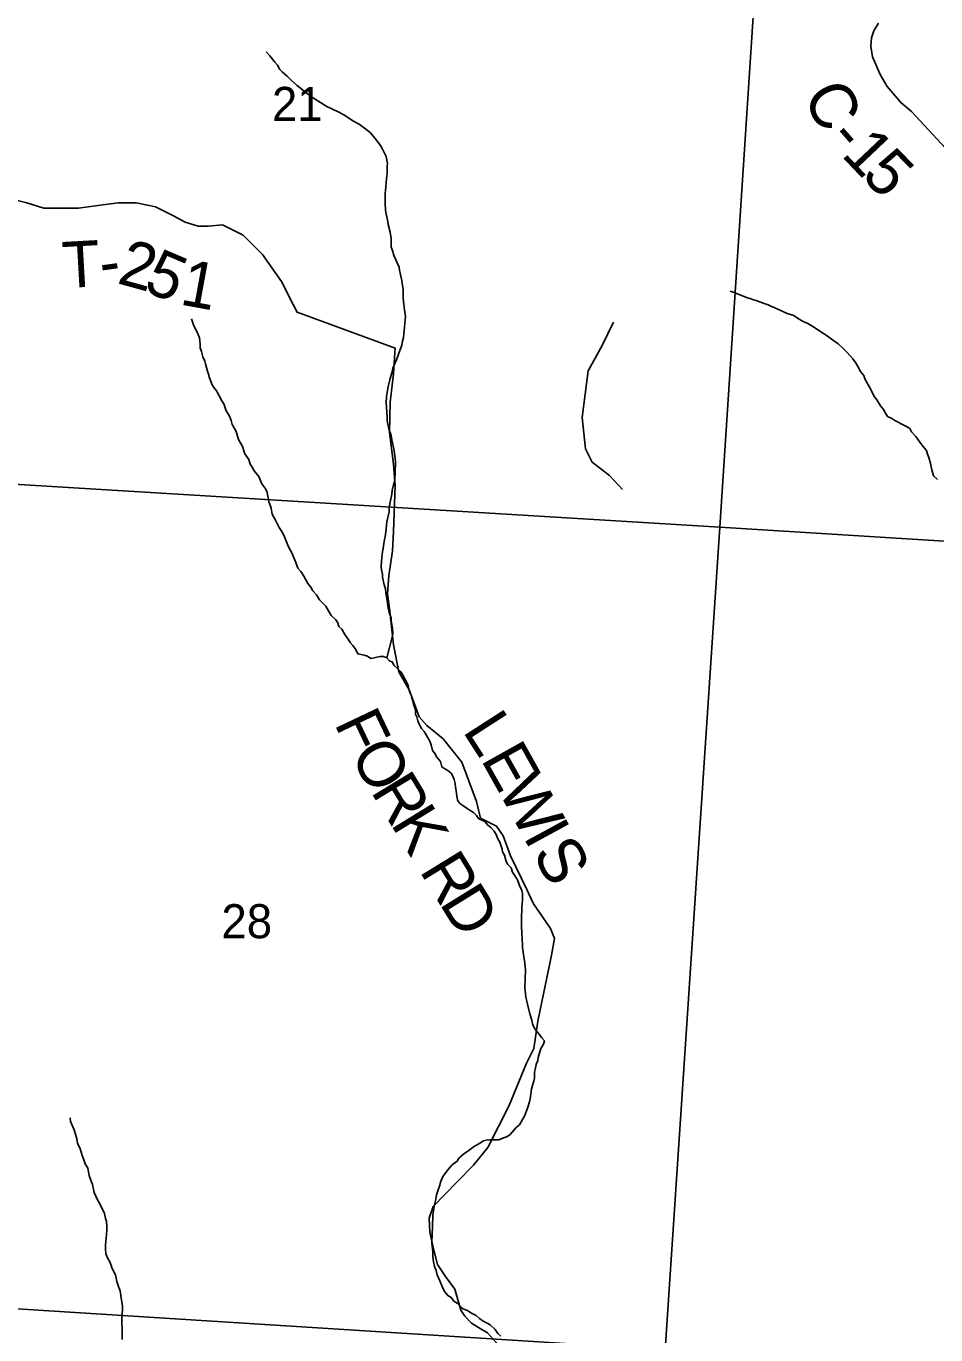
# Model space of a CAD drawing. Extents: x 0 to 34, y 0 to 22.
# Drawn here: x 4.939 to 6.056, y 16.966 to 18.575 of the extents above; entities that cross this region are included whole.
import ezdxf

# ---------------------------------------------------------------- set-up
doc = ezdxf.new("R2010")
doc.units = 0
for name, color, linetype in [('GM_X_County_Road', 7, 'Continuous'), ('GM_X_County_Road_Text', 7, 'Continuous'), ('GM_X_Minor_River', 7, 'Continuous'), ('GM_X_Section', 7, 'Continuous'), ('GM_X_Section_Text', 7, 'Continuous'), ('GM_X_Township_Road', 7, 'Continuous'), ('GM_X_Township_Road_Text', 7, 'Continuous'), ('GM_X_Township_ROW', 7, 'Continuous')]:
    doc.layers.add(name, color=color, linetype=linetype)

msp = doc.modelspace()

# ---------------------------------------------------------------- linework, layer by layer
at = {"layer": 'GM_X_County_Road'}
msp.add_lwpolyline([(5.9857, 18.5785), (5.9803, 18.569), (5.9774, 18.5607), (5.9765, 18.5503), (5.9786, 18.5374), (5.9877, 18.5154), (5.9965, 18.5009), (6.0135, 18.4806), (6.0263, 18.4702), (6.0945, 18.3967)], dxfattribs=at)
at = {"layer": 'GM_X_Minor_River'}
for points in [[(5.2805, 18.4945), (5.2716, 18.5018), (5.2645, 18.508), (5.2593, 18.5134), (5.2537, 18.5185), (5.2503, 18.5216), (5.2474, 18.5269), (5.2441, 18.5308), (5.2378, 18.5385), (5.2333, 18.5435)], [(5.3816, 17.7984), (5.3889, 17.8256), (5.389, 17.829), (5.3887, 17.8347), (5.3869, 17.8439), (5.387, 17.8477), (5.3848, 17.8542), (5.3831, 17.8622), (5.3821, 17.8687), (5.3804, 17.879), (5.38, 17.8832), (5.3786, 17.8881), (5.3765, 17.8977), (5.3766, 17.9015), (5.3752, 17.9068), (5.3748, 17.9102), (5.3753, 17.9175), (5.3754, 17.922), (5.3759, 17.9258), (5.3767, 17.9307), (5.3788, 17.944), (5.3797, 17.9474), (5.381, 17.9565), (5.3814, 17.9615), (5.3819, 17.9656), (5.3844, 17.9778), (5.3845, 17.9838), (5.3853, 17.988), (5.3878, 17.9997), (5.3882, 18.0043), (5.3915, 18.0179), (5.392, 18.0259), (5.3922, 18.0392), (5.3919, 18.0434), (5.3913, 18.0495), (5.3903, 18.0556), (5.3878, 18.0663), (5.3871, 18.0716), (5.3843, 18.08), (5.3822, 18.0899), (5.3822, 18.0937), (5.3816, 18.101), (5.381, 18.112), (5.3812, 18.1196), (5.3828, 18.1294), (5.3837, 18.1336), (5.3853, 18.1404), (5.3881, 18.1499), (5.389, 18.1544), (5.3937, 18.165), (5.3961, 18.1718), (5.4001, 18.1827), (5.4005, 18.1862), (5.4021, 18.1922), (5.4035, 18.2051), (5.404, 18.21), (5.4045, 18.218), (5.4035, 18.2264), (5.4025, 18.2329), (5.4018, 18.2405), (5.4019, 18.2447), (5.4016, 18.2507), (5.4006, 18.2591), (5.4003, 18.2625), (5.3989, 18.2675), (5.3971, 18.2748), (5.3968, 18.2786), (5.3939, 18.2847), (5.3899, 18.2943), (5.3892, 18.2981), (5.387, 18.3031), (5.3871, 18.3099), (5.3872, 18.3141), (5.3858, 18.3217), (5.3834, 18.3312), (5.383, 18.335), (5.3806, 18.3457), (5.3803, 18.3495), (5.3796, 18.356), (5.3797, 18.3602), (5.3795, 18.3697), (5.3799, 18.3731), (5.3804, 18.3773), (5.3813, 18.3871), (5.3822, 18.394), (5.3823, 18.4027), (5.3824, 18.4061), (5.381, 18.4149), (5.3748, 18.4268), (5.3689, 18.4348), (5.3615, 18.4437), (5.3544, 18.4495), (5.3476, 18.4546), (5.3398, 18.4585), (5.3296, 18.4655), (5.3221, 18.4694), (5.3082, 18.4761), (5.297, 18.4832), (5.2891, 18.4882), (5.2805, 18.4945)], [(6.0585, 18.0178), (6.0533, 18.0224), (6.0515, 18.0297), (6.0498, 18.0373), (6.0476, 18.0446), (6.0462, 18.0488), (6.0447, 18.0534), (6.0403, 18.0588), (6.0366, 18.0638), (6.0318, 18.0707), (6.0262, 18.0761), (6.0244, 18.0803), (6.0203, 18.083), (6.0161, 18.085), (6.0067, 18.0897), (6.0015, 18.0932), (5.997, 18.0952), (5.9944, 18.0991), (5.9918, 18.1037), (5.9881, 18.1083), (5.9837, 18.1156), (5.9811, 18.1194), (5.9786, 18.124), (5.976, 18.129), (5.969, 18.1413), (5.9679, 18.1455), (5.9639, 18.1505), (5.9606, 18.1566), (5.9576, 18.1616), (5.9543, 18.1659), (5.9476, 18.1736), (5.9416, 18.1794), (5.9361, 18.1844), (5.9293, 18.1895), (5.9226, 18.1941), (5.9162, 18.1984), (5.9072, 18.2047), (5.899, 18.2094), (5.8934, 18.2121), (5.8862, 18.216), (5.8817, 18.2191), (5.8735, 18.2219), (5.8667, 18.2251), (5.8584, 18.2287), (5.8535, 18.2306), (5.8502, 18.2322), (5.8464, 18.2338), (5.8407, 18.2358), (5.8355, 18.2378), (5.8321, 18.2386), (5.8279, 18.2402), (5.8238, 18.2414), (5.8189, 18.2434), (5.8133, 18.2454), (5.8084, 18.2477), (5.8035, 18.2493)], [(5.4427, 17.6768), (5.4413, 17.6806), (5.4379, 17.6845), (5.4362, 17.6918), (5.4344, 17.6963), (5.4299, 17.704), (5.4274, 17.7079), (5.4244, 17.7117), (5.4215, 17.7171), (5.42, 17.7213), (5.4186, 17.7259), (5.4171, 17.7293), (5.4168, 17.7347), (5.4147, 17.7415), (5.4133, 17.7465), (5.4115, 17.7526), (5.4097, 17.7568), (5.4079, 17.7645), (5.4064, 17.7683), (5.4031, 17.7741), (5.4013, 17.7775), (5.3991, 17.7813), (5.395, 17.7856), (5.3902, 17.7895), (5.3887, 17.7933), (5.3849, 17.7949), (5.3816, 17.7984), (5.3775, 17.8), (5.3733, 17.8), (5.3695, 17.7993), (5.3661, 17.7986), (5.3619, 17.7979), (5.3578, 17.8007), (5.354, 17.8019), (5.3461, 17.8035), (5.3435, 17.8089), (5.3398, 17.8135), (5.3365, 17.8174), (5.3343, 17.8216), (5.3302, 17.8274), (5.3265, 17.8339), (5.3228, 17.837), (5.3214, 17.8416), (5.3192, 17.8454), (5.3132, 17.8505), (5.3066, 17.862), (5.2991, 17.8697), (5.2955, 17.8759), (5.291, 17.8809), (5.2884, 17.8855), (5.2847, 17.8897), (5.2796, 17.8989), (5.2759, 17.9047), (5.2725, 17.9089), (5.27, 17.9158), (5.2646, 17.9285), (5.262, 17.9327), (5.2602, 17.9369), (5.2551, 17.9491), (5.2521, 17.9549), (5.2496, 17.9587), (5.2448, 17.9679), (5.2408, 17.9752), (5.2397, 17.9825), (5.2369, 17.9905), (5.2348, 18.0016), (5.233, 18.0058), (5.2281, 18.0123), (5.2245, 18.0215), (5.2186, 18.0284), (5.2164, 18.033), (5.2138, 18.0365), (5.212, 18.0422), (5.2072, 18.0492), (5.2043, 18.0583), (5.1996, 18.0668), (5.1967, 18.0767), (5.1945, 18.0805), (5.1915, 18.0852), (5.1905, 18.0901), (5.1883, 18.0955), (5.1839, 18.1031), (5.1818, 18.11), (5.1792, 18.1142), (5.1726, 18.1269), (5.1692, 18.1308), (5.167, 18.1342), (5.1638, 18.1426), (5.1627, 18.1472), (5.1613, 18.151), (5.1591, 18.1598), (5.1581, 18.1633), (5.1555, 18.1686), (5.1541, 18.1751), (5.1523, 18.1797), (5.1524, 18.1839), (5.1514, 18.1919), (5.1496, 18.1968), (5.1441, 18.208), (5.1416, 18.2152)], [(5.4701, 17.1835), (5.4759, 17.1884), (5.4828, 17.1936), (5.4893, 17.1984), (5.4927, 17.1999), (5.4962, 17.2021), (5.5004, 17.2047), (5.5038, 17.2058), (5.508, 17.2061), (5.5156, 17.206), (5.5194, 17.2063), (5.5251, 17.2085), (5.5293, 17.2099), (5.5331, 17.2125), (5.5408, 17.2211), (5.5447, 17.2245), (5.549, 17.232), (5.5509, 17.2354), (5.5533, 17.2418), (5.5549, 17.2464), (5.5569, 17.2528), (5.5577, 17.2566), (5.5595, 17.2687), (5.5623, 17.2782), (5.5631, 17.282), (5.5632, 17.2892), (5.564, 17.2926), (5.5653, 17.2987), (5.5673, 17.3036), (5.5677, 17.3074), (5.5709, 17.3184), (5.5741, 17.3236), (5.5753, 17.3278), (5.5723, 17.3316), (5.569, 17.3359), (5.566, 17.3394), (5.5623, 17.3444), (5.5609, 17.3489), (5.5598, 17.3531), (5.5573, 17.3608), (5.5562, 17.3658), (5.5545, 17.373), (5.5538, 17.3764), (5.5527, 17.3814), (5.552, 17.3856), (5.5514, 17.3932), (5.5516, 17.4042), (5.5522, 17.4145), (5.5519, 17.4191), (5.5509, 17.4267), (5.5495, 17.4336), (5.5491, 17.437), (5.5485, 17.4423), (5.5486, 17.4473), (5.5482, 17.4507), (5.5477, 17.4621), (5.5474, 17.4667), (5.5472, 17.4758), (5.5472, 17.4796), (5.5478, 17.4891), (5.5478, 17.4925), (5.5484, 17.5005), (5.5485, 17.5089), (5.5478, 17.5127), (5.5449, 17.5188), (5.5424, 17.5257), (5.5387, 17.5315), (5.5361, 17.5353), (5.5343, 17.5403), (5.5306, 17.5445), (5.5284, 17.5484), (5.5262, 17.556), (5.524, 17.5599), (5.5233, 17.5633), (5.5204, 17.5721), (5.5182, 17.5759), (5.5161, 17.5813), (5.5135, 17.5855), (5.5094, 17.5901), (5.506, 17.5929), (5.5023, 17.5975), (5.4948, 17.6007), (5.4918, 17.6049), (5.4881, 17.6084), (5.484, 17.6107), (5.4806, 17.6134), (5.475, 17.617), (5.4716, 17.6193), (5.4687, 17.6235), (5.4676, 17.6289), (5.467, 17.6346), (5.4663, 17.6399), (5.4656, 17.6441), (5.4646, 17.6491), (5.4628, 17.6533), (5.4606, 17.6567), (5.4568, 17.6602), (5.4531, 17.6622), (5.4493, 17.6645), (5.4475, 17.671), (5.4427, 17.6768)], [(5.0561, 16.9874), (5.057, 16.9977), (5.0571, 17.0022), (5.0557, 17.0091), (5.054, 17.0206), (5.0526, 17.0248), (5.05, 17.032), (5.0483, 17.0404), (5.0443, 17.0481), (5.0428, 17.0527), (5.041, 17.0569), (5.0388, 17.0604), (5.0366, 17.0661), (5.036, 17.0726), (5.036, 17.0771), (5.0374, 17.0893), (5.0375, 17.0958), (5.0376, 17.0992), (5.0373, 17.106), (5.0362, 17.1095), (5.0348, 17.1156), (5.0323, 17.1209), (5.0304, 17.1244), (5.0286, 17.1282), (5.0264, 17.1324), (5.022, 17.1416), (5.0199, 17.1512), (5.0185, 17.1554), (5.0159, 17.1623), (5.0142, 17.1711), (5.0109, 17.1768), (5.0095, 17.1814), (5.0073, 17.1868), (5.0048, 17.1952), (5.0015, 17.2021), (5.0008, 17.2074), (4.9976, 17.2185), (4.9932, 17.2285), (4.9926, 17.233)], [(5.522, 16.9647), (5.5182, 16.9682), (5.5149, 16.9732), (5.5086, 16.9787), (5.5052, 16.981), (5.4999, 16.9834), (5.4955, 16.9865), (5.4917, 16.9904), (5.485, 16.9935), (5.4808, 16.9962), (5.4752, 16.9986), (5.4718, 17.0013), (5.4681, 17.0052), (5.464, 17.0079), (5.4607, 17.0122), (5.4566, 17.0149), (5.4528, 17.0195), (5.4503, 17.0245), (5.4488, 17.028), (5.447, 17.0329), (5.4437, 17.0402), (5.4423, 17.0456), (5.4405, 17.0505), (5.4391, 17.0563), (5.4384, 17.0624), (5.4382, 17.0685), (5.4379, 17.0723), (5.4372, 17.0791), (5.4374, 17.0917), (5.4379, 17.0974), (5.4377, 17.1042), (5.4381, 17.1092), (5.4382, 17.1137), (5.4391, 17.119), (5.4399, 17.1247), (5.4415, 17.1311), (5.4428, 17.138), (5.444, 17.1421), (5.4468, 17.1505), (5.4476, 17.1539), (5.4504, 17.161), (5.4531, 17.1644), (5.457, 17.1697), (5.462, 17.1753), (5.4681, 17.1801), (5.4701, 17.1835)], [(5.0564, 16.9608), (5.0566, 16.9745), (5.0563, 16.9791), (5.0561, 16.9874)]]:
    msp.add_lwpolyline(points, dxfattribs=at)
at = {"layer": 'GM_X_Section'}
for points in [[(4.754, 19.0266), (5.8561, 18.9573), (5.7907, 17.959), (4.6942, 18.026)], [(5.8561, 18.9573), (6.9681, 18.8952), (6.9079, 17.8893), (5.7907, 17.959)], [(5.7907, 17.959), (5.7237, 16.9481), (4.636, 17.0167), (4.6942, 18.026)], [(6.9079, 17.8893), (6.8455, 16.8788), (5.7237, 16.9481), (5.7907, 17.959)], [(4.636, 17.0167), (5.7237, 16.9481), (5.6567, 15.9275), (4.5788, 15.9866)]]:
    msp.add_lwpolyline(points, close=True, dxfattribs=at)
at = {"layer": 'GM_X_Township_Road'}
for points in [[(5.2666, 18.233), (5.2525, 18.2612), (5.2288, 18.2944), (5.2051, 18.3181), (5.1798, 18.3308), (5.1624, 18.3292), (5.1498, 18.3292), (5.1339, 18.3339), (5.1197, 18.3418), (5.0976, 18.3529), (5.0739, 18.3576), (5.0518, 18.3576), (5.0265, 18.3545), (5.0028, 18.3513), (4.9601, 18.3513), (4.9396, 18.3576), (4.9143, 18.3639), (4.8969, 18.3671), (4.8779, 18.3734), (4.8416, 18.3803)], [(5.5829, 17.427), (5.5842, 17.4331), (5.5879, 17.4537), (5.5828, 17.466), (5.5732, 17.4802), (5.5618, 17.4962), (5.5536, 17.5136), (5.5335, 17.5552), (5.5248, 17.5799), (5.5165, 17.5917), (5.4968, 17.6016), (5.4919, 17.6218), (5.4737, 17.6704), (5.451, 17.6989), (5.4309, 17.7153), (5.4214, 17.7259), (5.4093, 17.7594), (5.3964, 17.7814), (5.39, 17.8145), (5.3851, 17.8593), (5.3824, 17.8772), (5.3843, 17.8992), (5.3889, 17.93), (5.39, 17.9539), (5.3919, 18.0102), (5.39, 18.036), (5.3851, 18.0759), (5.3858, 18.1127), (5.39, 18.1477), (5.3916, 18.1737)], [(5.5022, 16.9708), (5.4997, 16.9722), (5.4858, 16.9806), (5.4774, 16.9893), (5.4725, 16.9969), (5.4653, 17.0224), (5.454, 17.038), (5.4441, 17.0528), (5.4388, 17.0737), (5.4346, 17.0931), (5.4339, 17.1098), (5.4388, 17.1243), (5.468, 17.1547), (5.4884, 17.1748), (5.5059, 17.1965), (5.5316, 17.2474), (5.5532, 17.3002), (5.5623, 17.3185), (5.5672, 17.3519), (5.5829, 17.427)], [(5.5345, 16.9238), (5.5332, 16.9265), (5.5203, 16.9524), (5.5055, 16.9688), (5.5022, 16.9708)]]:
    msp.add_lwpolyline(points, dxfattribs=at)
at = {"layer": 'GM_X_Township_ROW'}
for points in [[(5.3916, 18.1737), (5.3919, 18.1792), (5.2714, 18.2232), (5.2666, 18.233)], [(5.6711, 18.0053), (5.6555, 18.0225), (5.6342, 18.0389), (5.626, 18.0553), (5.6219, 18.0938), (5.6293, 18.1511), (5.6465, 18.1823), (5.6604, 18.211)]]:
    msp.add_lwpolyline(points, dxfattribs=at)

# ---------------------------------------------------------------- texts
at = {"layer": 'GM_X_County_Road_Text'}
for s, rotation, p in [('C', 297.4188, (5.8921, 18.4894)), ('-', 311.1509, (5.9219, 18.4358)), ('1', 313.4805, (5.939, 18.4163)), ('5', 314.1169, (5.9635, 18.3904))]:
    msp.add_text(s, height=0.0568, rotation=rotation, dxfattribs=at).set_placement(p)
at = {"layer": 'GM_X_Section_Text'}
for s, p in [('21', (5.2406, 18.4584)), ('28', (5.1785, 17.4539))]:
    msp.add_text(s, height=0.04186, rotation=0, dxfattribs=at).set_placement(p)
at = {"layer": 'GM_X_Township_Road_Text'}
for s, rotation, p in [('T', 3.2256, (4.9844, 18.2528)), ('2', 344.6074, (5.0489, 18.2593)), ('5', 337.0855, (5.0808, 18.2506)), ('-', 7.9157, (5.0319, 18.2557)), ('1', 349.6165, (5.126, 18.2331)), ('F', 295.4616, (5.3166, 17.7182)), ('L', 302.7784, (5.474, 17.7089)), ('O', 300.1858, (5.3355, 17.679)), ('E', 299.2234, (5.4966, 17.6739)), ('W', 298.5611, (5.5172, 17.637)), ('R', 301.3419, (5.3612, 17.6347)), ('K', 301.5658, (5.3856, 17.5947)), ('I', 298.5583, (5.5487, 17.5792)), ('S', 298.5543, (5.5599, 17.5587)), ('R', 301.5938, (5.421, 17.5371)), ('D', 301.7555, (5.4455, 17.4972))]:
    msp.add_text(s, height=0.0568, rotation=rotation, dxfattribs=at).set_placement(p)

doc.saveas('drawing.dxf')
